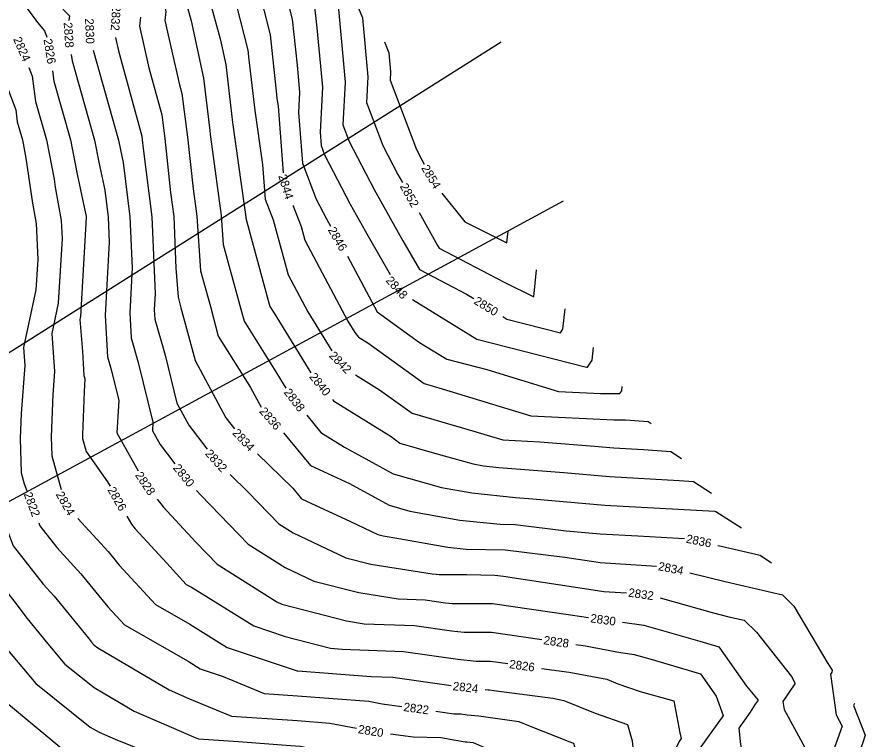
# Model space of a CAD drawing. Extents: x 1326424 to 1329294, y 1001359 to 1003823.
# Drawn here: x 1328321.7 to 1328519.8, y 1003069 to 1003237.8 of the extents above; entities that cross this region are included whole.
import ezdxf

# ---------------------------------------------------------------- set-up
doc = ezdxf.new("R2010")
doc.units = 0
for name, color, linetype in [('Default', 7, 'Continuous'), ('Prop Rem of Exist Asph Pvmt', 7, 'Continuous'), ('Scratch_Level_3', 7, 'Continuous')]:
    doc.layers.add(name, color=color, linetype=linetype)

msp = doc.modelspace()

# ---------------------------------------------------------------- linework, layer by layer
at = {"layer": 'Default'}
for p, q in [((1328184.23, 1003073.75), (1328434.81, 1003231.91)), ((1328177.22, 1003047.25), (1328449.39, 1003194.78))]:
    msp.add_line(p, q, dxfattribs=at)
at = {"layer": 'Prop Rem of Exist Asph Pvmt'}
for points in [[(1328364.5, 1003250), (1328364.93, 1003248.31), (1328369.2, 1003232.62), (1328370.48, 1003226.66), (1328371.13, 1003221.21), (1328372.06, 1003213.09), (1328374.82, 1003193.66), (1328375.09, 1003191.59), (1328375.15, 1003190.74), (1328380.65, 1003170.61), (1328380.78, 1003170.09), (1328381.76, 1003168.54), (1328390.39, 1003154.55)], [(1328395.42, 1003148.33), (1328395.64, 1003148.06), (1328409.1, 1003139.67), (1328411.16, 1003138.17), (1328419.25, 1003135.83), (1328428.26, 1003133.3), (1328430.71, 1003132.86), (1328434.24, 1003132.5), (1328449.43, 1003131.29), (1328460.09, 1003130.35), (1328476.4, 1003129.43), (1328479.69, 1003129.21), (1328483.9, 1003126.47)], [(1328319.28, 1003118.31), (1328320.82, 1003114.18), (1328327.81, 1003105.19), (1328330.37, 1003102.41), (1328338.4, 1003092.58), (1328339.16, 1003091.64), (1328339.72, 1003090.97), (1328340.59, 1003090.28), (1328357.29, 1003080.47), (1328362, 1003078.42), (1328371.79, 1003074.32), (1328387.26, 1003073.3), (1328394.78, 1003072.74), (1328401.04, 1003071.54)], [(1328408.93, 1003070.24), (1328414.29, 1003069.49), (1328420.74, 1003069.38), (1328426.4, 1003068.39), (1328426.81, 1003068.35), (1328428.23, 1003068.16), (1328434.26, 1003065.58), (1328438.93, 1003063.75), (1328444.47, 1003054.84), (1328445.63, 1003051.44), (1328444.03, 1003048.74), (1328440.53, 1003040.95), (1328442.81, 1003033.58), (1328443.58, 1003029.94), (1328444.11, 1003021.64), (1328444.15, 1003016.37), (1328444.82, 1003005.3), (1328444.64, 1002998.21)]]:
    msp.add_lwpolyline(points, dxfattribs=at)
at = {"layer": 'Scratch_Level_3'}
for points in [[(1328276.12, 1003287.31), (1328283.64, 1003293.72), (1328291.75, 1003295.71), (1328300.9, 1003299.63), (1328301.31, 1003296.08), (1328302.99, 1003293.46), (1328306.52, 1003282.91), (1328307.92, 1003280.2), (1328307.93, 1003279.96), (1328310.81, 1003273.25), (1328319.12, 1003258.75), (1328323.93, 1003250.7), (1328331.24, 1003240.84), (1328333.96, 1003237.98), (1328333.84, 1003236.89)], [(1328353.57, 1003294.77), (1328369.22, 1003267.69), (1328373.27, 1003261.61), (1328376.54, 1003250.52), (1328380.83, 1003233.57), (1328382.25, 1003220.44), (1328382.44, 1003218.73), (1328382.7, 1003216.92), (1328383.86, 1003201.35)], [(1328267.53, 1003275.82), (1328267.99, 1003276.06), (1328272.38, 1003279.07), (1328279.89, 1003283.21), (1328286.39, 1003288.75), (1328296.25, 1003291.17), (1328299.07, 1003285.81), (1328299.07, 1003285.8), (1328302.17, 1003279.82), (1328302.18, 1003279.29), (1328308.59, 1003264.4), (1328311.78, 1003258.82), (1328319.25, 1003246.32), (1328326.55, 1003236.48), (1328328.14, 1003234.5), (1328328.68, 1003233.03)], [(1328367.37, 1003283.2), (1328376.12, 1003268.07), (1328378.38, 1003264.67), (1328383.1, 1003248.68), (1328386, 1003237.2), (1328387.16, 1003226.47), (1328387.73, 1003220.19), (1328387.48, 1003215.42), (1328388.37, 1003203.55), (1328391.59, 1003195.15), (1328393.98, 1003190.56), (1328394.94, 1003188.83)], [(1328381.17, 1003271.64), (1328383.01, 1003268.45), (1328383.49, 1003267.73), (1328389.65, 1003246.85), (1328391.17, 1003240.82), (1328391.78, 1003235.19), (1328393.05, 1003221.37), (1328392.5, 1003210.85), (1328392.73, 1003207.73), (1328393.58, 1003205.52), (1328399.55, 1003194.01), (1328403.74, 1003186.5), (1328408.9, 1003177.55)], [(1328390.94, 1003258.72), (1328395.39, 1003247.76), (1328396.2, 1003245.01), (1328396.35, 1003244.45), (1328396.4, 1003243.92), (1328398.36, 1003222.54), (1328397.84, 1003212.57), (1328399.33, 1003208.64), (1328405.13, 1003197.46), (1328411.84, 1003185.44), (1328415.71, 1003178.71), (1328426.7, 1003173), (1328428.42, 1003171.94)], [(1328369.17, 1003255.13), (1328369.99, 1003252.35), (1328375.66, 1003229.95), (1328375.9, 1003227.75), (1328377.25, 1003215.91), (1328379.04, 1003203.3), (1328379.65, 1003195.2), (1328381.52, 1003190.31), (1328385.04, 1003177.45), (1328389.62, 1003168.84), (1328395.23, 1003159.75)], [(1328359.86, 1003246.64), (1328360.95, 1003242.26), (1328362.41, 1003236.88), (1328365.3, 1003223.45), (1328366.76, 1003211.19), (1328366.87, 1003210.26), (1328367.18, 1003208.04), (1328369.39, 1003191.39), (1328369.88, 1003184.59), (1328373.77, 1003170.34), (1328374.75, 1003166.63), (1328381.81, 1003155.41), (1328384.53, 1003151.01)], [(1328399.25, 1003245.32), (1328402.41, 1003237.53), (1328403.67, 1003223.72), (1328403.36, 1003217.76), (1328407.17, 1003207.72), (1328410.7, 1003200.91), (1328411.74, 1003199.05)], [(1328355.69, 1003242.39), (1328356.52, 1003239.06), (1328356.28, 1003236.94), (1328359.67, 1003221.91), (1328360.23, 1003219.84), (1328361.58, 1003209.63), (1328362.85, 1003197.56), (1328363.69, 1003191.2), (1328364.61, 1003178.44), (1328366.9, 1003170.07), (1328368.71, 1003163.17), (1328376.29, 1003151.13), (1328378.76, 1003146.56)], [(1328350.6, 1003237.67), (1328350.36, 1003235.58), (1328352.55, 1003225.88), (1328355.54, 1003214.87), (1328356.27, 1003209.33), (1328357.6, 1003196.73), (1328358.32, 1003191.09), (1328358.85, 1003179.05), (1328359.34, 1003172.29), (1328360.02, 1003169.8), (1328361.31, 1003164.91), (1328362.59, 1003160.34), (1328363.31, 1003157.43), (1328370.51, 1003144.1), (1328372.49, 1003141.53)], [(1328344.73, 1003232.96), (1328345.43, 1003229.86), (1328350.86, 1003209.9), (1328350.97, 1003209.03), (1328351.18, 1003207.04), (1328353.21, 1003191.06), (1328354.02, 1003173.13), (1328353.79, 1003169.3), (1328353.93, 1003167.15), (1328356.3, 1003158.69), (1328359.07, 1003147.52), (1328361.87, 1003142.34), (1328366.17, 1003136.78)], [(1328407.55, 1003231.92), (1328408.58, 1003229.38), (1328408.99, 1003224.9), (1328408.89, 1003222.96), (1328415.01, 1003206.81), (1328416.27, 1003204.37), (1328416.82, 1003203.38)], [(1328339.48, 1003229.96), (1328345.42, 1003208.98), (1328345.87, 1003206.67), (1328346.49, 1003203.74), (1328348.11, 1003191.03), (1328348.65, 1003179.11), (1328348.04, 1003168.64), (1328348.41, 1003162.75), (1328350.01, 1003157.03), (1328353.48, 1003143.07), (1328353.35, 1003141.05), (1328355.16, 1003137.84), (1328358.62, 1003133.34)], [(1328334.38, 1003228.95), (1328334.58, 1003227.48), (1328339.81, 1003208.99), (1328340.81, 1003203.83), (1328342.21, 1003197.3), (1328343.01, 1003191), (1328343.28, 1003185.09), (1328342.28, 1003167.97), (1328342.89, 1003158.35), (1328343.72, 1003155.38), (1328345.52, 1003148.12), (1328345.05, 1003140.57), (1328350.03, 1003131.7)], [(1328317.96, 1003225.35), (1328321.42, 1003216.01), (1328321.79, 1003213.22), (1328322.98, 1003209.03), (1328323.81, 1003204.73), (1328325.33, 1003194.21), (1328326.19, 1003189.47), (1328326.57, 1003181.08), (1328326.16, 1003173.95), (1328323.22, 1003160.51), (1328323.55, 1003156.27), (1328322.68, 1003145.09), (1328322.46, 1003139.23), (1328322.72, 1003131.18), (1328323.43, 1003128.65), (1328324.04, 1003127.03)], [(1328324.52, 1003225.95), (1328325.27, 1003223.95), (1328326.05, 1003217.97), (1328328.59, 1003209.02), (1328330.38, 1003199.82), (1328330.65, 1003197.96), (1328332.04, 1003190.21), (1328332.24, 1003185.98), (1328331.37, 1003170.83), (1328329.83, 1003163.77), (1328330.52, 1003154.87), (1328330.1, 1003149.52), (1328329.73, 1003139.66), (1328329.87, 1003135.2), (1328332.07, 1003127.35)], [(1328329.99, 1003225.17), (1328330.32, 1003222.73), (1328334.2, 1003209.01), (1328335.76, 1003200.99), (1328337.87, 1003191.13), (1328337.9, 1003190.96), (1328337.9, 1003190.89), (1328336.59, 1003167.72), (1328336.43, 1003167.03), (1328337.01, 1003159.55), (1328337.37, 1003153.95), (1328337.43, 1003153.72), (1328337.57, 1003153.17), (1328337.38, 1003150.23), (1328337, 1003140.09), (1328337.03, 1003139.21), (1328337.87, 1003136.19), (1328342.88, 1003129.14), (1328343.47, 1003128.1)], [(1328420.94, 1003196.54), (1328426.34, 1003189.86), (1328436.12, 1003184.94), (1328436.41, 1003187.71)], [(1328386.16, 1003193.75), (1328388.07, 1003188.78), (1328388.96, 1003185.55), (1328399, 1003166.68), (1328400.66, 1003163.98), (1328401.51, 1003162.94), (1328403.7, 1003161.58), (1328416.81, 1003152.11), (1328421.06, 1003150.88), (1328441.73, 1003144.56), (1328461.1, 1003143.58), (1328463.85, 1003143.57), (1328469.15, 1003143.21), (1328469.88, 1003142.73)], [(1328415.64, 1003192.06), (1328419.93, 1003184.37), (1328420.33, 1003183.68), (1328435.48, 1003175.81), (1328442.42, 1003172.32), (1328443.08, 1003178.63)], [(1328398.88, 1003181.87), (1328405.83, 1003168.84), (1328415.77, 1003161.66), (1328422.11, 1003157.74), (1328431.49, 1003155.35), (1328448.22, 1003150.24), (1328458, 1003149.75), (1328462.55, 1003149.73), (1328462.96, 1003150.34), (1328463.07, 1003151.4)], [(1328414.07, 1003171.76), (1328429.13, 1003162.45), (1328454.4, 1003156.02), (1328454.72, 1003155.92), (1328454.9, 1003155.91), (1328454.98, 1003155.91), (1328456.1, 1003157.56), (1328456.41, 1003160.48)], [(1328435.23, 1003167.74), (1328436.16, 1003167.16), (1328448.69, 1003163.97), (1328449.24, 1003164.79), (1328449.74, 1003169.56)], [(1328400.77, 1003154.13), (1328406.4, 1003150.62), (1328413.99, 1003145.14), (1328428.62, 1003140.91), (1328435.23, 1003138.89), (1328443.81, 1003138.45), (1328456.64, 1003137.43), (1328461.15, 1003137.03), (1328468.05, 1003136.65), (1328474.42, 1003136.21), (1328476.89, 1003134.6)], [(1328389.41, 1003144.68), (1328392.7, 1003140.62), (1328398.21, 1003137.18), (1328409.55, 1003130.97), (1328420.86, 1003127.78), (1328427.93, 1003126.51), (1328438.15, 1003125.48), (1328442.21, 1003125.15), (1328459.02, 1003123.67), (1328484.74, 1003122.22), (1328484.97, 1003122.2), (1328490.92, 1003118.35)], [(1328384, 1003140.56), (1328390.3, 1003132.95), (1328399.37, 1003128.72), (1328408.66, 1003123.63), (1328413.46, 1003122.27), (1328425.15, 1003120.17), (1328434.54, 1003119.22), (1328438.08, 1003119.15), (1328449.98, 1003117.69), (1328457.96, 1003116.98), (1328466.69, 1003116.49), (1328477.6, 1003115.84)], [(1328377.91, 1003135.67), (1328386.12, 1003127.65), (1328388.17, 1003125.17), (1328399.62, 1003119.82), (1328406.04, 1003116.78), (1328407.25, 1003116.47), (1328410.91, 1003115.89), (1328422.37, 1003113.83), (1328426.61, 1003113.4), (1328435.72, 1003113.22), (1328449.68, 1003111.51), (1328457.43, 1003110.33), (1328457.95, 1003110.26), (1328471.09, 1003109.41)], [(1328371.51, 1003130.84), (1328375.75, 1003126.69), (1328382.91, 1003119.28), (1328386.2, 1003117.2), (1328398.54, 1003111.36), (1328404.4, 1003109.84), (1328418.67, 1003107.58), (1328419.63, 1003107.54), (1328420.34, 1003107.44), (1328420.58, 1003107.42), (1328426.78, 1003107.42), (1328433.36, 1003107.29), (1328435.33, 1003107.05), (1328457.34, 1003103.7), (1328458.81, 1003103.5), (1328464.08, 1003103.16)], [(1328363.63, 1003127.11), (1328364.69, 1003125.97), (1328375.69, 1003114.57), (1328384.32, 1003109.11), (1328391.05, 1003105.93), (1328401.54, 1003103.22), (1328410.74, 1003101.76), (1328417.09, 1003101.52), (1328421.79, 1003100.86), (1328423.38, 1003100.69), (1328432.79, 1003100.7), (1328450.97, 1003098.02), (1328455.23, 1003097.37)], [(1328354.47, 1003125.07), (1328355.84, 1003123.29), (1328363.51, 1003115.01), (1328368.48, 1003109.86), (1328382.45, 1003101.03), (1328383.55, 1003100.51), (1328398.69, 1003096.59), (1328402.8, 1003095.94), (1328414.56, 1003095.51), (1328423.24, 1003094.27), (1328426.18, 1003093.97), (1328432.56, 1003093.97), (1328444.33, 1003092.24)], [(1328295.43, 1003120.72), (1328296.82, 1003115.36), (1328297.78, 1003108.91), (1328301.12, 1003099.54), (1328307.55, 1003091.27), (1328311.21, 1003086.48), (1328318.92, 1003077.93), (1328319.3, 1003077.48), (1328320.17, 1003076.79), (1328334.93, 1003064.53), (1328340.34, 1003062.87), (1328350.37, 1003058.82), (1328362.42, 1003056.89), (1328362.83, 1003056.85)], [(1328335.93, 1003120.52), (1328342.98, 1003112.86), (1328345.62, 1003109.63), (1328354.07, 1003100.41), (1328362.09, 1003095.83), (1328370.8, 1003090.43), (1328387.18, 1003084.93), (1328387.2, 1003084.92), (1328387.22, 1003084.92), (1328387.32, 1003084.91), (1328404.46, 1003083.65), (1328409.48, 1003083.47), (1328423.14, 1003081.53)], [(1328347.39, 1003121.12), (1328348.46, 1003119.23), (1328349.34, 1003118.09), (1328356.72, 1003110.11), (1328361.27, 1003105.15), (1328362.47, 1003104.46), (1328377.05, 1003095.43), (1328384.38, 1003092.97), (1328394.91, 1003090.22), (1328397.67, 1003090.01), (1328412.02, 1003089.49), (1328424.69, 1003087.69), (1328428.98, 1003087.24), (1328432.34, 1003087.24), (1328436.33, 1003086.65)], [(1328304.22, 1003118.62), (1328306.27, 1003110.7), (1328306.64, 1003108.22), (1328307.93, 1003104.61), (1328317.43, 1003092.39), (1328317.77, 1003091.95), (1328317.86, 1003091.83), (1328326.11, 1003081.98), (1328338.84, 1003071.81), (1328340.93, 1003070.58), (1328344.65, 1003068.96), (1328357.16, 1003063.91), (1328362.76, 1003063.01), (1328372.83, 1003061.87), (1328376.12, 1003061.62), (1328377.19, 1003061.54)], [(1328312.24, 1003118.46), (1328313.66, 1003111.87), (1328314.54, 1003109.52), (1328321.19, 1003100.98), (1328324.07, 1003097.18), (1328328.51, 1003091.73), (1328332.91, 1003086.47), (1328339.71, 1003081.04), (1328349.11, 1003075.53), (1328362.92, 1003069.51), (1328364.08, 1003069.03), (1328373.44, 1003068.41), (1328385.59, 1003067.49), (1328387.91, 1003067.31), (1328389.33, 1003066.99)], [(1328326.83, 1003119.53), (1328327.09, 1003118.83), (1328331.05, 1003113.74), (1328336.67, 1003107.63), (1328342.97, 1003099.92), (1328346.87, 1003095.67), (1328361.71, 1003087.2), (1328364.54, 1003085.44), (1328369.88, 1003083.65), (1328379.49, 1003079.62), (1328387.24, 1003079.11), (1328403.9, 1003077.86), (1328407.03, 1003077.26), (1328411.63, 1003076.62)], [(1328485.42, 1003114.25), (1328486.19, 1003114.06), (1328495.27, 1003111.94), (1328497.93, 1003110.22)], [(1328478.9, 1003107.82), (1328487.1, 1003105.83), (1328500.48, 1003102.7), (1328503.18, 1003100.07), (1328511.09, 1003086.67), (1328512.1, 1003085.12), (1328512.07, 1003084.61), (1328511.75, 1003084.15), (1328513.04, 1003074.67), (1328514.48, 1003072.03), (1328511.51, 1003063.73), (1328509.81, 1003059.14), (1328508.87, 1003056.28), (1328500.9, 1003035.32), (1328500.63, 1003032.11), (1328500.61, 1003031.48)], [(1328471.97, 1003102.02), (1328484.09, 1003098.54), (1328488, 1003097.59), (1328491.53, 1003096.77), (1328494.42, 1003093.96), (1328502.58, 1003083.62), (1328503.42, 1003082.11), (1328503.4, 1003081.88), (1328500.63, 1003077.78), (1328500.89, 1003075.9), (1328506.21, 1003066.18), (1328505.7, 1003064.76), (1328505.41, 1003063.98), (1328505.25, 1003063.49), (1328494.52, 1003035.26), (1328494.43, 1003034.25), (1328494.38, 1003032.77), (1328493.4, 1003025.73)], [(1328463.16, 1003096.28), (1328468.14, 1003095.62), (1328481.18, 1003091.88), (1328485.61, 1003090.58), (1328492.08, 1003081.33), (1328494.83, 1003078.12), (1328494.14, 1003077.14), (1328492.97, 1003075.31), (1328490.28, 1003071.54), (1328490.69, 1003067.69), (1328492.17, 1003060.97), (1328495.07, 1003058.87), (1328488.86, 1003041.45), (1328487.19, 1003034.56), (1328485.16, 1003021.35)], [(1328452.25, 1003091.09), (1328454.52, 1003090.79), (1328461.82, 1003089.37), (1328463.19, 1003089.13), (1328465.89, 1003088.77), (1328470.04, 1003087.58), (1328481.37, 1003084.25), (1328485, 1003079.06), (1328486.68, 1003074.5), (1328486.43, 1003074.11), (1328484.2, 1003070.98), (1328481.41, 1003067.16), (1328480.55, 1003065.48), (1328480.71, 1003062.01), (1328483, 1003052.38), (1328483.39, 1003051.2), (1328482.46, 1003047.32), (1328479.06, 1003033.3), (1328478.58, 1003030.22), (1328477.17, 1003018.54)], [(1328444.25, 1003085.52), (1328450.71, 1003084.66), (1328459.48, 1003082.96), (1328462.02, 1003081.9), (1328467.24, 1003080.12), (1328475.14, 1003077.91), (1328476.56, 1003070.46), (1328476.85, 1003069.13), (1328476.5, 1003068.65), (1328472, 1003059.88), (1328472.03, 1003059.21), (1328472.53, 1003046.9), (1328473.58, 1003043.69), (1328471.63, 1003035.54), (1328469.87, 1003021.32), (1328468.92, 1003013.53), (1328468.98, 1003011.78)], [(1328431.08, 1003080.59), (1328431.78, 1003080.51), (1328432.12, 1003080.51), (1328433.1, 1003080.37), (1328446.91, 1003078.53), (1328449.43, 1003078.04), (1328456.73, 1003075.02), (1328464.35, 1003072.41), (1328465.4, 1003068.57), (1328465.98, 1003063.11), (1328463.86, 1003059.02), (1328459.68, 1003052.29), (1328461.93, 1003041.44), (1328463.66, 1003037.37), (1328463.73, 1003035.22), (1328461.14, 1003015.84), (1328460.98, 1003009.69), (1328460.98, 1003009.54)], [(1328517.3, 1003077.3), (1328517.12, 1003076.83), (1328519.79, 1003069.94), (1328519.28, 1003068.18), (1328517.31, 1003062.69), (1328514.21, 1003054.3), (1328512.49, 1003049.06), (1328507.29, 1003035.38), (1328506.83, 1003029.98), (1328506.59, 1003022.12), (1328505.85, 1003016.78), (1328504.8, 1003010.88), (1328504.72, 1003006.21), (1328505.57, 1002999.35), (1328508.67, 1002980.51)], [(1328419.55, 1003075.51), (1328423.73, 1003074.93), (1328425.42, 1003074.9), (1328426.9, 1003074.64), (1328429.61, 1003074.39), (1328438.96, 1003073.11), (1328441.22, 1003072.15), (1328450.82, 1003068.39), (1328451.43, 1003068.13), (1328451.74, 1003068.03), (1328452.17, 1003066.47), (1328455.35, 1003057.14), (1328450.03, 1003048.22), (1328448.96, 1003045.84), (1328450.18, 1003041.9), (1328453.47, 1003034.18), (1328453.76, 1003024.18), (1328453.24, 1003020.31), (1328452.82, 1003004.53)]]:
    msp.add_lwpolyline(points, dxfattribs=at)

# ---------------------------------------------------------------- texts
at = {"layer": 'Prop Rem of Exist Asph Pvmt'}
for s, rotation, p in [('2840', 308.937, (1328389.87, 1003153.6)), ('2820', 350.6875, (1328401.27, 1003070.39))]:
    msp.add_text(s, height=2, rotation=rotation, dxfattribs=at).set_placement(p)
at = {"layer": 'Scratch_Level_3'}
for s, rotation, p in [('2832', 266.54, (1328343.97, 1003240.52)), ('2830', 272.0704, (1328337.62, 1003237.37)), ('2828', 273.9182, (1328332.62, 1003236.43)), ('2824', 293.594, (1328320.78, 1003232.58)), ('2826', 279.4644, (1328327.9, 1003232.5)), ('2854', 301.0454, (1328416.07, 1003202.44)), ('2844', 286.8858, (1328382.73, 1003200.63)), ('2852', 299.1611, (1328411.07, 1003198.2)), ('2846', 299.4783, (1328394.28, 1003187.98)), ('2848', 311.7587, (1328407.72, 1003176.07)), ('2850', 328.3018, (1328428.25, 1003170.87)), ('2842', 314.6045, (1328394.46, 1003158.44)), ('2838', 307.6093, (1328383.93, 1003149.99)), ('2836', 311.1278, (1328378.19, 1003145.5)), ('2834', 312.8018, (1328371.91, 1003140.4)), ('2832', 311.9477, (1328365.53, 1003135.61)), ('2830', 308.8211, (1328358.06, 1003132.31)), ('2828', 303.8459, (1328349.21, 1003130.66)), ('2822', 290.446, (1328323.25, 1003126.29)), ('2824', 299.4316, (1328330.71, 1003126.19)), ('2826', 299.328, (1328342.8, 1003127.25)), ('2836', 348.5116, (1328477.86, 1003114.92)), ('2834', 348.4582, (1328471.34, 1003108.49)), ('2832', 351.7665, (1328464.4, 1003102.3)), ('2830', 352.179, (1328455.54, 1003096.3)), ('2828', 351.7692, (1328444.6, 1003091.18)), ('2826', 351.8597, (1328436.6, 1003085.59)), ('2824', 353.2096, (1328423.43, 1003080.44)), ('2822', 352.0522, (1328411.9, 1003075.57))]:
    msp.add_text(s, height=2, rotation=rotation, dxfattribs=at).set_placement(p)

doc.saveas('drawing.dxf')
